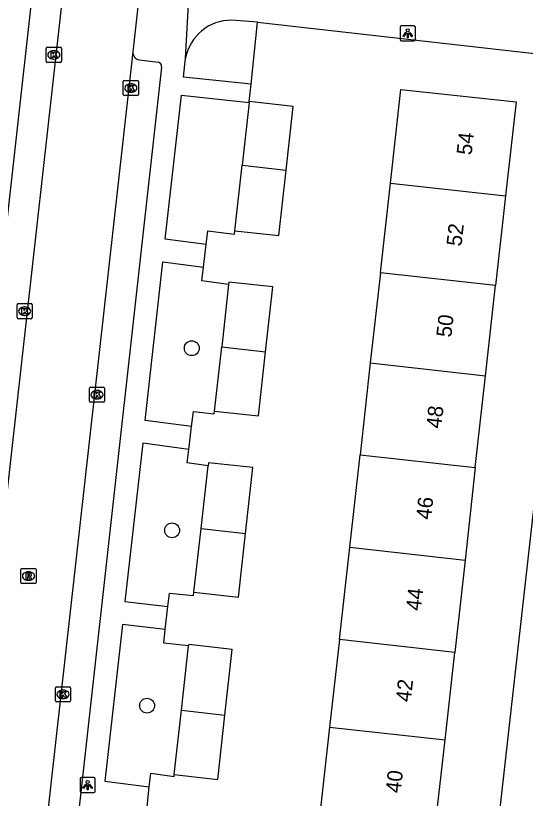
# Model space of a CAD drawing. Extents: x 161928 to 163055, y 386475 to 387428.
# Drawn here: x 162118.7 to 162152.3, y 387186 to 387237.6 of the extents above; entities that cross this region are included whole.
import ezdxf

# ---------------------------------------------------------------- set-up
doc = ezdxf.new("R2010")
doc.units = 0
for name, color, linetype in [('IMGEO_Boom', 7, 'Continuous'), ('IMGEO_Groenvoorziening', 7, 'Continuous'), ('IMGEO_Kolk', 7, 'Continuous'), ('IMGEO_Lichtpunt', 7, 'Continuous'), ('IMGEO_Pand', 7, 'Continuous'), ('IMGEO_Pand_nummerreeks', 7, 'Continuous'), ('IMGEO_Rijbaan_lokaal_open', 7, 'Continuous'), ('IMGEO_Rioolput', 7, 'Continuous'), ('IMGEO_Voetpad_open', 7, 'Continuous')]:
    doc.layers.add(name, color=color, linetype=linetype)

msp = doc.modelspace()

# ---------------------------------------------------------------- linework, layer by layer
at = {"layer": 'IMGEO_Boom'}
for centre in [(162130.329, 387215.712), (162129.034, 387203.703), (162127.385, 387192.138)]:
    msp.add_circle(centre, 0.489, dxfattribs=at)
at = {"layer": 'IMGEO_Groenvoorziening'}
for points in [[(162134.243, 387233.133), (162134.66, 387237.211)], [(162131.276, 387222.56), (162131.385, 387223.453), (162133.146, 387223.234), (162133.172, 387223.457)], [(162132.758, 387219.903), (162130.996, 387220.151), (162131.1, 387221.045)], [(162130.314, 387210.55), (162130.442, 387211.53), (162131.809, 387211.387), (162131.831, 387211.571)], [(162131.4, 387207.965), (162130.034, 387208.16), (162130.139, 387209.043)], [(162128.752, 387198.676), (162128.85, 387199.55), (162130.451, 387199.41), (162130.472, 387199.619)], [(162130.115, 387196.076), (162128.484, 387196.27), (162128.582, 387197.16)], [(162127.511, 387186.795), (162127.626, 387187.688), (162129.158, 387187.459), (162129.173, 387187.596)]]:
    msp.add_lwpolyline(points, dxfattribs=at)
at = {"layer": 'IMGEO_Kolk'}
for p, q in [((162120.736, 387234.631), (162120.736, 387235.483)), ((162120.811, 387235.557), (162121.663, 387235.557)), ((162121.737, 387235.483), (162121.737, 387234.631)), ((162121.224, 387235.337), (162121.249, 387235.337)), ((162121.663, 387234.557), (162120.811, 387234.557)), ((162121.247, 387234.777), (162121.222, 387234.777)), ((162125.89, 387233.368), (162126.742, 387233.368)), ((162125.815, 387232.442), (162125.815, 387233.294)), ((162126.303, 387233.148), (162126.328, 387233.148)), ((162126.816, 387233.294), (162126.816, 387232.442)), ((162126.742, 387232.368), (162125.89, 387232.368)), ((162126.326, 387232.588), (162126.301, 387232.588)), ((162118.813, 387217.728), (162118.813, 387218.58)), ((162118.888, 387218.654), (162119.74, 387218.654)), ((162119.301, 387218.434), (162119.326, 387218.434)), ((162119.814, 387218.58), (162119.814, 387217.728)), ((162119.324, 387217.874), (162119.299, 387217.874)), ((162119.74, 387217.654), (162118.888, 387217.654)), ((162123.582, 387212.219), (162123.582, 387213.071)), ((162123.657, 387213.145), (162124.509, 387213.145)), ((162124.07, 387212.925), (162124.095, 387212.925)), ((162124.583, 387213.071), (162124.583, 387212.219)), ((162124.509, 387212.145), (162123.657, 387212.145)), ((162124.093, 387212.365), (162124.068, 387212.365)), ((162121.344, 387192.459), (162121.344, 387193.311)), ((162121.419, 387193.385), (162122.271, 387193.385)), ((162121.832, 387193.165), (162121.857, 387193.165)), ((162122.345, 387193.311), (162122.345, 387192.459)), ((162121.855, 387192.605), (162121.83, 387192.605)), ((162122.271, 387192.385), (162121.419, 387192.385))]:
    msp.add_line(p, q, dxfattribs=at)
for points in [[(162120.736, 387234.631), (162120.736, 387235.483)], [(162120.811, 387235.557), (162121.663, 387235.557)], [(162121.737, 387235.483), (162121.737, 387234.631)], [(162121.057, 387235.257), (162121.18, 387235.257), (162121.18, 387235.106), (162121.31, 387235.257), (162121.474, 387235.257), (162121.328, 387235.106), (162121.481, 387234.857), (162121.329, 387234.857), (162121.244, 387235.021), (162121.18, 387234.954), (162121.18, 387234.857), (162121.057, 387234.857), (162121.057, 387235.257)], [(162121.663, 387234.557), (162120.811, 387234.557)], [(162125.89, 387233.368), (162126.742, 387233.368)], [(162125.815, 387232.442), (162125.815, 387233.294)], [(162126.136, 387233.068), (162126.259, 387233.068), (162126.259, 387232.917), (162126.389, 387233.068), (162126.553, 387233.068), (162126.407, 387232.917), (162126.56, 387232.668), (162126.408, 387232.668), (162126.323, 387232.832), (162126.259, 387232.765), (162126.259, 387232.668), (162126.136, 387232.668), (162126.136, 387233.068)], [(162126.816, 387233.294), (162126.816, 387232.442)], [(162126.742, 387232.368), (162125.89, 387232.368)], [(162118.813, 387217.728), (162118.813, 387218.58)], [(162118.888, 387218.654), (162119.74, 387218.654)], [(162119.134, 387218.354), (162119.257, 387218.354), (162119.257, 387218.203), (162119.387, 387218.354), (162119.551, 387218.354), (162119.405, 387218.203), (162119.558, 387217.954), (162119.406, 387217.954), (162119.321, 387218.118), (162119.257, 387218.051), (162119.257, 387217.954), (162119.134, 387217.954), (162119.134, 387218.354)], [(162119.814, 387218.58), (162119.814, 387217.728)], [(162119.74, 387217.654), (162118.888, 387217.654)], [(162123.582, 387212.219), (162123.582, 387213.071)], [(162123.657, 387213.145), (162124.509, 387213.145)], [(162123.903, 387212.845), (162124.026, 387212.845), (162124.026, 387212.694), (162124.156, 387212.845), (162124.32, 387212.845), (162124.174, 387212.694), (162124.327, 387212.445), (162124.175, 387212.445), (162124.09, 387212.609), (162124.026, 387212.542), (162124.026, 387212.445), (162123.903, 387212.445), (162123.903, 387212.845)], [(162124.583, 387213.071), (162124.583, 387212.219)], [(162124.509, 387212.145), (162123.657, 387212.145)], [(162121.344, 387192.459), (162121.344, 387193.311)], [(162121.419, 387193.385), (162122.271, 387193.385)], [(162121.665, 387193.085), (162121.788, 387193.085), (162121.788, 387192.934), (162121.918, 387193.085), (162122.082, 387193.085), (162121.936, 387192.934), (162122.089, 387192.685), (162121.937, 387192.685), (162121.852, 387192.849), (162121.788, 387192.782), (162121.788, 387192.685), (162121.665, 387192.685), (162121.665, 387193.085)], [(162122.345, 387193.311), (162122.345, 387192.459)], [(162122.271, 387192.385), (162121.419, 387192.385)]]:
    msp.add_lwpolyline(points, dxfattribs=at)
for centre, start, end in [((162120.813, 387235.481), 91.552, 178.448), ((162120.813, 387235.481), 91.552, 178.448), ((162121.661, 387235.481), 1.552, 88.448), ((162121.661, 387235.481), 1.552, 88.448), ((162120.813, 387234.633), 181.552, 268.448), ((162120.813, 387234.633), 181.552, 268.448), ((162121.661, 387234.633), 271.552, 358.448), ((162121.661, 387234.633), 271.552, 358.448), ((162125.892, 387233.292), 91.552, 178.448), ((162125.892, 387233.292), 91.552, 178.448), ((162126.74, 387233.292), 1.552, 88.448), ((162126.74, 387233.292), 1.552, 88.448), ((162125.892, 387232.444), 181.552, 268.448), ((162125.892, 387232.444), 181.552, 268.448), ((162126.74, 387232.444), 271.552, 358.448), ((162126.74, 387232.444), 271.552, 358.448), ((162118.89, 387218.578), 91.552, 178.448), ((162118.89, 387218.578), 91.552, 178.448), ((162119.738, 387218.578), 1.552, 88.448), ((162119.738, 387218.578), 1.552, 88.448), ((162118.89, 387217.73), 181.552, 268.448), ((162118.89, 387217.73), 181.552, 268.448), ((162119.738, 387217.73), 271.552, 358.448), ((162119.738, 387217.73), 271.552, 358.448), ((162123.659, 387213.069), 91.552, 178.448), ((162123.659, 387213.069), 91.552, 178.448), ((162124.507, 387213.069), 1.552, 88.448), ((162124.507, 387213.069), 1.552, 88.448), ((162123.659, 387212.221), 181.552, 268.448), ((162123.659, 387212.221), 181.552, 268.448), ((162124.507, 387212.221), 271.552, 358.448), ((162124.507, 387212.221), 271.552, 358.448), ((162121.421, 387193.309), 91.552, 178.448), ((162121.421, 387193.309), 91.552, 178.448), ((162122.269, 387193.309), 1.552, 88.448), ((162122.269, 387193.309), 1.552, 88.448), ((162121.421, 387192.461), 181.552, 268.448), ((162121.421, 387192.461), 181.552, 268.448), ((162122.269, 387192.461), 271.552, 358.448), ((162122.269, 387192.461), 271.552, 358.448)]:
    msp.add_arc(centre, 0.0765, start, end, dxfattribs=at)
for centre, major_axis, ratio, start_param, end_param in [((162121.223, 387235.057), (-0.387, 0.002), 0.722429, 4.712389, 7.853982), ((162121.248, 387235.057), (-0.39, 0.002), 0.717154, 1.570796, 4.712389), ((162126.302, 387232.868), (-0.387, 0.002), 0.722429, 4.712389, 7.853982), ((162126.327, 387232.868), (-0.39, 0.002), 0.717154, 1.570796, 4.712389), ((162119.3, 387218.154), (-0.387, 0.002), 0.722429, 4.712389, 7.853982), ((162119.325, 387218.154), (-0.39, 0.002), 0.717154, 1.570796, 4.712389), ((162124.069, 387212.645), (-0.387, 0.002), 0.722429, 4.712389, 7.853982), ((162124.094, 387212.645), (-0.39, 0.002), 0.717154, 1.570796, 4.712389), ((162121.831, 387192.885), (-0.387, 0.002), 0.722429, 4.712389, 7.853982), ((162121.856, 387192.885), (-0.39, 0.002), 0.717154, 1.570796, 4.712389)]:
    msp.add_ellipse(centre, major_axis=major_axis, ratio=ratio, start_param=start_param, end_param=end_param, dxfattribs=at)
at = {"layer": 'IMGEO_Lichtpunt'}
for p, q in [((162144.969, 387236.973), (162144.161, 387236.973)), ((162144.969, 387236.973), (162144.161, 387236.973)), ((162144.067, 387236.878), (162144.067, 387236.071)), ((162144.067, 387236.878), (162144.067, 387236.071)), ((162145.063, 387236.071), (162145.063, 387236.878)), ((162145.063, 387236.071), (162145.063, 387236.878)), ((162144.161, 387235.977), (162144.969, 387235.977)), ((162144.161, 387235.977), (162144.969, 387235.977)), ((162123.869, 387187.402), (162123.061, 387187.402)), ((162123.869, 387187.402), (162123.061, 387187.402)), ((162122.967, 387187.307), (162122.967, 387186.5)), ((162122.967, 387187.307), (162122.967, 387186.5)), ((162123.963, 387186.5), (162123.963, 387187.307)), ((162123.963, 387186.5), (162123.963, 387187.307)), ((162123.061, 387186.406), (162123.869, 387186.406)), ((162123.061, 387186.406), (162123.869, 387186.406))]:
    msp.add_line(p, q, dxfattribs=at)
for points in [[(162144.441, 387236.542), (162144.48, 387236.514), (162144.292, 387236.252), (162144.254, 387236.279), (162144.441, 387236.542)], [(162144.543, 387236.494), (162144.59, 387236.494), (162144.59, 387236.172), (162144.543, 387236.172), (162144.543, 387236.494)], [(162144.653, 387236.514), (162144.691, 387236.541), (162144.878, 387236.279), (162144.839, 387236.251), (162144.653, 387236.514)], [(162123.341, 387186.971), (162123.38, 387186.943), (162123.192, 387186.681), (162123.154, 387186.708), (162123.341, 387186.971)], [(162123.443, 387186.923), (162123.49, 387186.923), (162123.49, 387186.601), (162123.443, 387186.601), (162123.443, 387186.923)], [(162123.553, 387186.943), (162123.591, 387186.97), (162123.778, 387186.708), (162123.739, 387186.68), (162123.553, 387186.943)]]:
    msp.add_lwpolyline(points, dxfattribs=at)
for centre in [(162144.566, 387236.676), (162123.466, 387187.105)]:
    msp.add_circle(centre, 0.0994, dxfattribs=at)
for centre, start, end in [((162144.161, 387236.878), 90, 180), ((162144.161, 387236.878), 90, 180), ((162144.969, 387236.878), 0, 90), ((162144.969, 387236.878), 0, 90), ((162144.161, 387236.071), 180, 270), ((162144.161, 387236.071), 180, 270), ((162144.969, 387236.071), 270, 0), ((162144.969, 387236.071), 270, 360), ((162123.061, 387187.307), 90, 180), ((162123.061, 387187.307), 90, 180), ((162123.869, 387187.307), 0, 90), ((162123.869, 387187.307), 0, 90), ((162123.061, 387186.5), 180, 270), ((162123.061, 387186.5), 180, 270), ((162123.869, 387186.5), 270, 0), ((162123.869, 387186.5), 270, 360)]:
    msp.add_arc(centre, 0.0946, start, end, dxfattribs=at)
at = {"layer": 'IMGEO_Pand'}
for points in [[(162143.421, 387226.606), (162144.11, 387232.778), (162151.698, 387231.962), (162151.008, 387225.759)], [(162134.114, 387231.925), (162133.652, 387227.771)], [(162134.114, 387231.925), (162134.12, 387231.981)], [(162136.552, 387227.449), (162137.02, 387231.658), (162134.12, 387231.981)], [(162133.172, 387223.457), (162133.652, 387227.771)], [(162133.652, 387227.771), (162136.552, 387227.449)], [(162133.172, 387223.457), (162136.072, 387223.134), (162136.552, 387227.449)], [(162142.761, 387220.691), (162143.421, 387226.606)], [(162143.421, 387226.606), (162151.008, 387225.759)], [(162151.008, 387225.759), (162150.351, 387219.844)], [(162142.761, 387220.691), (162142.096, 387214.739)], [(162150.351, 387219.844), (162142.761, 387220.691)], [(162132.758, 387219.903), (162132.301, 387215.796)], [(162135.195, 387215.474), (162135.671, 387219.755), (162132.777, 387220.076), (162132.758, 387219.903)], [(162149.689, 387213.891), (162150.351, 387219.844)], [(162131.831, 387211.571), (162132.301, 387215.796)], [(162132.301, 387215.796), (162135.195, 387215.474)], [(162131.831, 387211.571), (162134.725, 387211.249), (162135.195, 387215.474)], [(162142.096, 387214.739), (162141.421, 387208.691)], [(162142.096, 387214.739), (162149.689, 387213.891)], [(162149.016, 387207.843), (162149.689, 387213.891)], [(162140.74, 387202.594), (162141.421, 387208.691)], [(162141.421, 387208.691), (162149.016, 387207.843)], [(162133.877, 387203.494), (162134.36, 387207.836), (162131.422, 387208.162), (162131.4, 387207.965)], [(162130.939, 387203.821), (162131.4, 387207.965)], [(162149.016, 387207.843), (162148.338, 387201.746)], [(162130.472, 387199.619), (162130.939, 387203.821)], [(162130.472, 387199.619), (162133.41, 387199.292), (162133.877, 387203.494)], [(162130.939, 387203.821), (162133.877, 387203.494)], [(162140.059, 387196.496), (162140.74, 387202.594)], [(162140.74, 387202.594), (162148.338, 387201.746)], [(162148.338, 387201.746), (162147.66, 387195.647)], [(162132.511, 387191.52), (162132.992, 387195.847), (162130.125, 387196.166), (162130.115, 387196.076)], [(162140.059, 387196.496), (162139.416, 387190.729)], [(162147.66, 387195.647), (162140.059, 387196.496)], [(162129.644, 387191.839), (162130.115, 387196.076)], [(162147.019, 387189.88), (162147.66, 387195.647)], [(162129.173, 387187.596), (162129.644, 387191.839)], [(162129.173, 387187.596), (162132.04, 387187.277), (162132.511, 387191.52)], [(162129.644, 387191.839), (162132.511, 387191.52)], [(162139.416, 387190.729), (162138.751, 387184.779)], [(162139.416, 387190.729), (162147.019, 387189.88)], [(162146.357, 387183.93), (162147.019, 387189.88)]]:
    msp.add_lwpolyline(points, dxfattribs=at)
at = {"layer": 'IMGEO_Rijbaan_lokaal_open'}
for points in [[(162130.777, 387274.349), (162128.563, 387254.234), (162126.448, 387235.259)], [(162117.072, 387196.521), (162123.558, 387254.485), (162123.853, 387257.116)], [(162126.448, 387235.259), (162119.765, 387175.585), (162118.995, 387168.628)]]:
    msp.add_lwpolyline(points, dxfattribs=at)
at = {"layer": 'IMGEO_Rioolput'}
for p, q in [((162119.065, 387200.26), (162119.065, 387201.112)), ((162119.14, 387201.186), (162119.992, 387201.186)), ((162119.553, 387200.966), (162119.578, 387200.966)), ((162120.066, 387201.112), (162120.066, 387200.26)), ((162119.576, 387200.406), (162119.551, 387200.406)), ((162119.992, 387200.186), (162119.14, 387200.186))]:
    msp.add_line(p, q, dxfattribs=at)
for points in [[(162119.065, 387200.26), (162119.065, 387201.112)], [(162119.14, 387201.186), (162119.992, 387201.186)], [(162119.654, 387200.884), (162119.402, 387200.886), (162119.402, 387200.486)], [(162119.58, 387200.805), (162119.526, 387200.805), (162119.526, 387200.724)], [(162120.066, 387201.112), (162120.066, 387200.26)], [(162119.402, 387200.486), (162119.526, 387200.486), (162119.526, 387200.648), (162119.537, 387200.648)], [(162119.526, 387200.724), (162119.578, 387200.724)], [(162119.584, 387200.619), (162119.655, 387200.486), (162119.795, 387200.486), (162119.73, 387200.612)], [(162119.992, 387200.186), (162119.14, 387200.186)]]:
    msp.add_lwpolyline(points, dxfattribs=at)
for centre, radius, start, end in [((162119.142, 387201.11), 0.0765, 91.552, 178.448), ((162119.142, 387201.11), 0.0765, 91.552, 178.448), ((162119.586, 387200.709), 0.0964, 77.0061, 93.1865), ((162119.6, 387200.766), 0.0378, 276.6634, 79.6772), ((162119.653, 387200.774), 0.109, 350.3612, 89.416), ((162119.99, 387201.11), 0.0765, 1.552, 88.448), ((162119.99, 387201.11), 0.0765, 1.552, 88.448), ((162119.536, 387200.595), 0.0533, 26.0293, 88.6989), ((162119.562, 387200.913), 0.19, 274.7715, 282.9687), ((162119.651, 387200.774), 0.112, 277.5842, 350.9817), ((162119.635, 387200.559), 0.108, 29.5134, 73.7905), ((162119.142, 387200.262), 0.0765, 181.552, 268.448), ((162119.142, 387200.262), 0.0765, 181.552, 268.448), ((162119.99, 387200.262), 0.0765, 271.552, 358.448), ((162119.99, 387200.262), 0.0765, 271.552, 358.448)]:
    msp.add_arc(centre, radius, start, end, dxfattribs=at)
for centre, major_axis, ratio, start_param, end_param in [((162119.552, 387200.686), (-0.387, 0.002), 0.722429, 4.712389, 7.853982), ((162119.577, 387200.686), (-0.39, 0.002), 0.717154, 1.570796, 4.712389)]:
    msp.add_ellipse(centre, major_axis=major_axis, ratio=ratio, start_param=start_param, end_param=end_param, dxfattribs=at)
at = {"layer": 'IMGEO_Voetpad_open'}
for points in [[(162115.182, 387197.475), (162121.574, 387254.719), (162121.808, 387256.578)], [(162129.922, 387234.839), (162130.355, 387242.733)], [(162134.66, 387237.211), (162132.954, 387237.341)], [(162134.66, 387237.211), (162154.481, 387234.979)], [(162126.876, 387234.737), (162128.108, 387234.577)], [(162134.243, 387233.133), (162129.785, 387233.594), (162129.922, 387234.839)], [(162128.339, 387234.25), (162121.784, 387175.371), (162121.082, 387169.158)], [(162134.12, 387231.981), (162134.243, 387233.133)], [(162155.986, 387233.092), (162148.298, 387164.623)], [(162131.276, 387222.56), (162128.58, 387222.902), (162129.661, 387232.389), (162134.114, 387231.925)], [(162131.1, 387221.045), (162131.276, 387222.56)], [(162130.314, 387210.55), (162127.262, 387210.948), (162128.431, 387221.4), (162131.1, 387221.045)], [(162130.139, 387209.043), (162130.314, 387210.55)], [(162130.139, 387209.043), (162127.109, 387209.445), (162125.918, 387198.999), (162128.752, 387198.676)], [(162128.582, 387197.16), (162128.752, 387198.676)], [(162128.582, 387197.16), (162125.765, 387197.5), (162124.603, 387187.17), (162127.511, 387186.795)], [(162127.362, 387185.278), (162127.511, 387186.795)]]:
    msp.add_lwpolyline(points, dxfattribs=at)
for centre, radius, start, end in [((162132.925, 387234.288), 3.053, 89.4596, 169.5992), ((162126.931, 387235.219), 0.485, 175.2544, 263.4438), ((162128.024, 387234.273), 0.316, 355.8717, 74.6048)]:
    msp.add_arc(centre, radius, start, end, dxfattribs=at)

# ---------------------------------------------------------------- texts
at = {"layer": 'IMGEO_Pand_nummerreeks'}
for s, p in [('54', (162148.768, 387228.414)), ('52', (162148.099, 387222.401)), ('50', (162147.431, 387216.397)), ('48', (162146.763, 387210.386)), ('46', (162146.095, 387204.373)), ('44', (162145.426, 387198.362)), ('42', (162144.758, 387192.349)), ('40', (162144.09, 387186.345))]:
    msp.add_text(s, height=1, rotation=83.6555, dxfattribs=at).set_placement(p)

doc.saveas('drawing.dxf')
